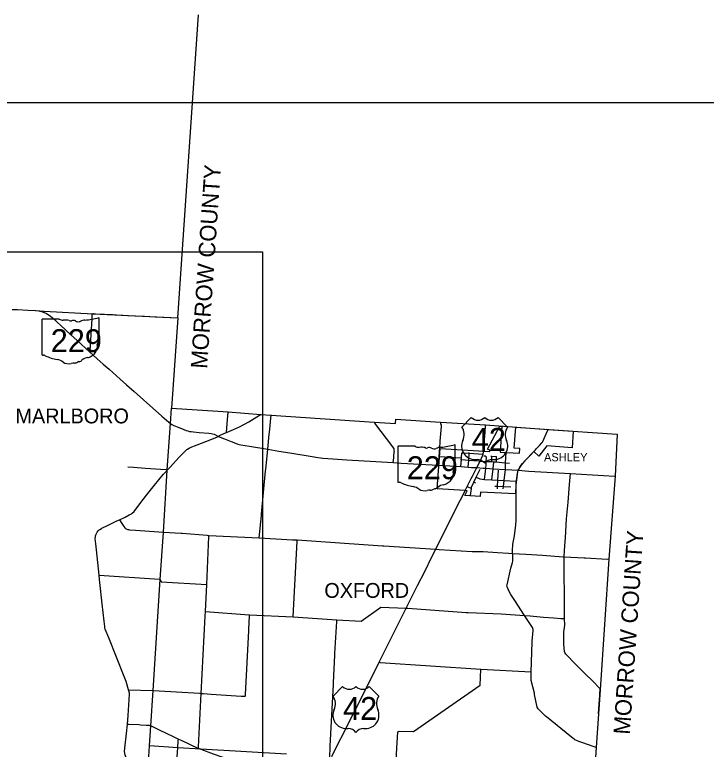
# Model space of a CAD drawing. Extents: x 1729596 to 1925846, y 659247 to 911751.
# Drawn here: x 1813555 to 1855559, y 860705 to 905333 of the extents above; entities that cross this region are included whole.
import ezdxf

# ---------------------------------------------------------------- set-up
doc = ezdxf.new("R2010")
doc.units = 0
for name, color, linetype in [('GM_X_Adjacent_County', 7, 'Continuous'), ('GM_X_Adjacent_County_Text', 7, 'Continuous'), ('GM_X_City_Street', 7, 'Continuous'), ('GM_X_Corporation', 7, 'Continuous'), ('GM_X_Corporation_Text', 7, 'Continuous'), ('GM_X_County', 7, 'Continuous'), ('GM_X_County_Road', 7, 'Continuous'), ('GM_X_State_Route', 7, 'Continuous'), ('GM_X_State_Shield', 7, 'Continuous'), ('GM_X_Township', 7, 'Continuous'), ('GM_X_Township_Road', 7, 'Continuous'), ('GM_X_Township_Text', 7, 'Continuous'), ('GM_X_US_Route', 7, 'Continuous'), ('GM_X_US_Shield', 7, 'Continuous'), ('SC_Scratch1', 7, 'Continuous'), ('SH_Data', 7, 'Continuous')]:
    doc.layers.add(name, color=color, linetype=linetype)

msp = doc.modelspace()

# ---------------------------------------------------------------- linework, layer by layer
at = {"layer": 'GM_X_Adjacent_County'}
msp.add_line((1823458, 886911), (1824723, 905333), dxfattribs=at)
at = {"layer": 'GM_X_City_Street'}
for points in [[(1845108, 878825), (1845186, 878908), (1845242, 878975), (1845432, 879171), (1845571, 879323), (1845601, 879368), (1845923, 880061), (1845958, 880137)], [(1840712, 878711), (1840771, 878720), (1841162, 878693), (1842005, 878635)], [(1841096, 877846), (1841141, 878272), (1841162, 878693), (1841165, 878729)], [(1843359, 877702), (1843365, 878107), (1843394, 878741)], [(1839341, 878485), (1840692, 878411)], [(1840624, 878310), (1840684, 878302), (1841141, 878272), (1841739, 878225)], [(1840655, 877877), (1840684, 878302), (1840692, 878411), (1840712, 878711)], [(1842195, 878194), (1842196, 878198), (1842207, 878423), (1842204, 878453), (1842189, 878476), (1842156, 878505), (1842118, 878523), (1842051, 878515)], [(1842480, 878523), (1842536, 878518), (1842809, 878492)], [(1842538, 878180), (1842536, 878518)], [(1842823, 878163), (1842809, 878492)], [(1841739, 878225), (1841815, 878219), (1842196, 878198), (1842538, 878180), (1842649, 878172), (1842823, 878163), (1843332, 878109)], [(1842164, 877756), (1842167, 877780), (1842180, 877986), (1842195, 878194)], [(1842531, 877075), (1842621, 877751), (1842649, 878172)], [(1843332, 878109), (1843335, 878108), (1843365, 878107), (1843598, 878093)], [(1841290, 876572), (1841275, 876591), (1841439, 876928), (1841591, 877241), (1841826, 877723)], [(1842082, 877102), (1842164, 877756)], [(1842882, 876677), (1842882, 876677), (1842882, 876684), (1842900, 877054), (1842928, 877653)], [(1843238, 876648), (1843241, 876673), (1843277, 877031), (1843359, 877702)], [(1841591, 877241), (1841805, 877127), (1842082, 877102), (1842094, 877101), (1842531, 877075), (1842900, 877054), (1843277, 877031), (1843995, 876989)], [(1841039, 876677), (1841303, 876558)], [(1841244, 876119), (1841303, 876558), (1841290, 876572)], [(1841439, 876928), (1841534, 876885)], [(1842709, 876689), (1842882, 876684), (1843220, 876674), (1843220, 876674)], [(1842875, 876522), (1842882, 876677)], [(1843220, 876674), (1843241, 876673), (1843680, 876660)], [(1843230, 876537), (1843238, 876642), (1843238, 876648)]]:
    msp.add_lwpolyline(points, dxfattribs=at)
at = {"layer": 'GM_X_Corporation'}
msp.add_lwpolyline([(1839212, 876522), (1839395, 878979), (1842403, 878797), (1842406, 878874), (1842276, 878944), (1843026, 880333), (1843137, 880326), (1843037, 878758), (1844222, 878701), (1844237, 878976), (1843894, 879006), (1843983, 880269), (1847478, 880034), (1847407, 879013), (1845866, 879149), (1845394, 878513), (1845080, 878796), (1844533, 878238), (1844393, 878064), (1844314, 877970), (1844271, 877898), (1844236, 877846), (1844178, 877730), (1844140, 877653), (1844101, 877578), (1844075, 877468), (1843989, 876865), (1843985, 876781), (1843972, 876227), (1841843, 876336), (1841816, 876073), (1840902, 876121), (1841027, 876414), (1840914, 876421)], close=True, dxfattribs=at)
at = {"layer": 'GM_X_County'}
msp.add_lwpolyline([(1813443, 887429), (1813717, 887422), (1814360, 887388), (1814847, 887358), (1815353, 887328), (1818316, 887169), (1823458, 886911), (1823082, 881429), (1826517, 881205), (1828513, 881052), (1829123, 881005), (1835395, 880574), (1836682, 880495), (1836708, 880754), (1839410, 880574), (1842150, 880416), (1845959, 880135), (1850147, 879854), (1850017, 877290), (1849634, 872258), (1849106, 864311), (1848864, 860810), (1848787, 859601)], dxfattribs=at)
at = {"layer": 'GM_X_County_Road'}
for points in [[(1826404, 879946), (1826423, 879954), (1826844, 880138), (1827215, 880304), (1827767, 880596), (1828264, 880901), (1828526, 881056)], [(1826423, 879954), (1826479, 880739), (1826518, 881195)], [(1822822, 877662), (1822979, 877822), (1823573, 878476), (1824013, 878909), (1824059, 878945), (1824151, 879002), (1824217, 879033), (1824631, 879211), (1825422, 879515), (1825871, 879688), (1825923, 879717)], [(1825923, 879717), (1825991, 879759), (1826404, 879946)], [(1844140, 877653), (1844178, 877730), (1844236, 877846), (1844271, 877898), (1844314, 877970), (1844393, 878064), (1844672, 878363), (1844876, 878580), (1845108, 878825)], [(1818695, 874040), (1818726, 874065), (1818820, 874127), (1818849, 874146), (1819230, 874331), (1819753, 874577), (1819917, 874653), (1820258, 874816), (1820515, 874948), (1820647, 875011), (1820694, 875046), (1820805, 875160), (1821161, 875608), (1821552, 876138), (1821797, 876450), (1822043, 876750), (1822580, 877393), (1822787, 877627), (1822822, 877662)], [(1844920, 865421), (1844988, 867215), (1844990, 867274), (1845035, 867925), (1845034, 867981), (1845022, 868042), (1845000, 868095), (1844527, 868834), (1843932, 869740), (1843693, 870106), (1843565, 870325), (1843478, 870530), (1843453, 870621), (1843455, 870702), (1843691, 871703), (1843783, 872054), (1843799, 872125), (1843808, 872218), (1843813, 872294), (1843800, 872513), (1843796, 872610), (1843794, 872719), (1843797, 872872), (1843799, 873058), (1843810, 873171), (1843903, 873683), (1843995, 874339), (1844011, 874603), (1844010, 875790), (1844011, 876128), (1844012, 876758), (1844119, 877561), (1844140, 877653)], [(1820462, 864324), (1820315, 864828), (1820199, 865126), (1819267, 867478), (1819059, 868009), (1819037, 868087), (1819024, 868161), (1818988, 868490), (1818871, 869545), (1818714, 871024), (1818688, 871275), (1818522, 872824), (1818481, 873185), (1818449, 873518), (1818456, 873613), (1818468, 873675), (1818498, 873766), (1818559, 873888), (1818627, 873984), (1818695, 874040)], [(1824699, 860768), (1824709, 860807), (1824715, 860860), (1824883, 864100), (1825114, 868796), (1825134, 869072), (1825228, 870716), (1825347, 873642), (1825350, 873697)], [(1825350, 873697), (1828404, 873550), (1830426, 873436), (1830706, 873421), (1835899, 873073), (1835968, 873069), (1839135, 872864)], [(1839135, 872864), (1839344, 872852), (1841345, 872730), (1841421, 872727), (1842003, 872716), (1842870, 872667), (1843552, 872620), (1843796, 872610)], [(1848869, 860822), (1848289, 861017), (1848127, 861070), (1847820, 861177), (1847644, 861252), (1847581, 861290), (1847540, 861317), (1847370, 861450), (1845855, 862679), (1845795, 862727), (1845378, 863132), (1845338, 863172), (1845282, 863256), (1845130, 864033), (1845116, 864109), (1844927, 864878), (1844914, 864930), (1844919, 865353), (1844920, 865421)], [(1819979, 856052), (1820004, 856221), (1820093, 856849), (1820106, 856948), (1820253, 859267), (1820256, 859321), (1820308, 860164), (1820312, 860243), (1820295, 860293), (1820272, 860358), (1820219, 860562), (1820238, 860767), (1820341, 861658), (1820408, 862232), (1820454, 862755), (1820524, 864057), (1820528, 864114), (1820480, 864265), (1820462, 864324)], [(1820408, 862232), (1820494, 862231), (1821085, 862203), (1821196, 862192), (1821533, 862179), (1821692, 862169), (1821732, 862161)], [(1821732, 862161), (1821747, 862158), (1821783, 862149), (1821820, 862138), (1821852, 862127), (1822363, 861870), (1822764, 861678), (1823175, 861477), (1823506, 861322), (1823697, 861236), (1824174, 861011), (1824367, 860911), (1824699, 860768)], [(1824699, 860768), (1824857, 860710), (1825612, 860430), (1826656, 860059), (1826853, 859982), (1826971, 859934), (1827258, 859768), (1827710, 859527), (1828254, 859247), (1828432, 859153), (1828513, 859123), (1828584, 859112), (1829052, 859088), (1829917, 859051), (1830145, 859048), (1831204, 858991), (1831412, 858982), (1831846, 858956), (1831978, 858953), (1832140, 858950)]]:
    msp.add_lwpolyline(points, dxfattribs=at)
at = {"layer": 'GM_X_State_Route'}
for points in [[(1813408, 887426), (1813443, 887429), (1813717, 887422), (1814360, 887388), (1814824, 887360)], [(1814824, 887360), (1814847, 887358), (1815015, 887333), (1815089, 887321), (1815189, 887294), (1815338, 887242), (1815486, 887171), (1815704, 887032), (1815841, 886918), (1816128, 886656), (1816355, 886449), (1816954, 885901), (1817356, 885538), (1818106, 884845), (1818568, 884430), (1818934, 884102), (1819283, 883790), (1819954, 883190), (1820355, 882842), (1820806, 882440), (1821377, 881933), (1822496, 880940), (1822775, 880699), (1822923, 880569), (1823026, 880489), (1823096, 880443), (1823229, 880369), (1823524, 880245), (1823681, 880185), (1823974, 880072), (1824071, 880043), (1824169, 880019), (1824269, 880002), (1824418, 879984), (1824766, 879955), (1825340, 879913), (1825491, 879897), (1825574, 879880), (1825668, 879848), (1825923, 879717), (1826289, 879572), (1826707, 879409), (1826973, 879302), (1827103, 879251), (1827193, 879225), (1827284, 879205), (1827814, 879113), (1828926, 878930), (1829588, 878819), (1830263, 878712), (1831616, 878486), (1831957, 878431), (1832136, 878410), (1832267, 878397), (1832870, 878356), (1833733, 878300), (1836550, 878131), (1837033, 878098), (1838904, 877988), (1839306, 877964)], [(1839306, 877964), (1840655, 877877), (1841096, 877846), (1841303, 877834)], [(1841303, 877834), (1841619, 877817)], [(1841619, 877817), (1842011, 877788), (1842144, 877781)], [(1842144, 877781), (1842167, 877780), (1842611, 877751), (1842621, 877751), (1843359, 877702), (1844140, 877653)], [(1844140, 877653), (1844783, 877609), (1847310, 877457), (1849978, 877293)]]:
    msp.add_lwpolyline(points, dxfattribs=at)
at = {"layer": 'GM_X_State_Shield'}
for p, q in [((1815205, 886800), (1815205, 884687)), ((1815205, 886800), (1815205, 884687)), ((1816258, 886837), (1815239, 886837)), ((1816258, 886837), (1815239, 886837)), ((1818685, 885784), (1818685, 886889)), ((1818685, 885784), (1818685, 886889)), ((1818685, 885784), (1818685, 885784)), ((1818685, 885784), (1818685, 885784)), ((1840307, 878062), (1840307, 879167)), ((1840307, 878062), (1840307, 879167)), ((1836826, 879078), (1836826, 876965)), ((1836826, 879078), (1836826, 876965)), ((1837880, 879115), (1836860, 879115)), ((1837880, 879115), (1836860, 879115)), ((1840306, 878062), (1840307, 878062)), ((1840306, 878062), (1840307, 878062))]:
    msp.add_line(p, q, dxfattribs=at)
for centre, major_axis, start_param, end_param in [((1815244, 886805), (40.3, 0), 1.712693, 3.28349), ((1815244, 886805), (40.3, 0), 1.712693, 3.28349), ((1816501, 887082), (391, 0), 4.042523, 4.731795), ((1816501, 887082), (391, 0), 4.042523, 4.731795), ((1816630, 885650), (1404, 0), 1.404758, 1.657858), ((1816630, 885650), (1404, 0), 1.404758, 1.657858), ((1816949, 886816), (113, 0), 3.836095, 5.185415), ((1816949, 886816), (113, 0), 3.836095, 5.185415), ((1817115, 886572), (235, 0), 0.950623, 2.079405), ((1817115, 886572), (235, 0), 0.950623, 2.079405), ((1817916, 886191), (743, 0), 1.699011, 2.107814), ((1817916, 886191), (743, 0), 1.699011, 2.107814), ((1817445, 889718), (3691, 0), 4.814394, 5.042369), ((1817445, 889718), (3691, 0), 4.814394, 5.042369), ((1818646, 886894), (38.7, 0), 6.141152, 7.989035), ((1818646, 886894), (38.7, 0), 6.141152, 7.989035), ((1817418, 886907), (282, 0), 4.081561, 5.145723), ((1817418, 886907), (282, 0), 4.081561, 5.145723), ((1818824, 885321), (262, 0), 2.387724, 3.262537), ((1818824, 885321), (262, 0), 2.387724, 3.262537), ((1818676, 885703), (60, 0), 1.883978, 3.671073), ((1818676, 885703), (60, 0), 1.883978, 3.671073), ((1818295, 885563), (360, 0), 5.934695, 6.695948), ((1818295, 885563), (360, 0), 5.934695, 6.695948), ((1818644, 885779), (41.5, 0), 5.05454, 6.418171), ((1818644, 885779), (41.5, 0), 5.05454, 6.418171), ((1817652, 885180), (923, 0), 5.101752, 6.440018), ((1817652, 885180), (923, 0), 5.101752, 6.440018), ((1815245, 884683), (40.7, 0), 3.00124, 4.508301), ((1815245, 884683), (40.7, 0), 3.00124, 4.508301), ((1815251, 884899), (310, 0), 4.665946, 4.897461), ((1815251, 884899), (310, 0), 4.665946, 4.897461), ((1815314, 884565), (112, 0), 0.519207, 1.627899), ((1815314, 884565), (112, 0), 0.519207, 1.627899), ((1816728, 886464), (2665, 0), 4.195997, 4.488961), ((1816728, 886464), (2665, 0), 4.195997, 4.488961), ((1815933, 883738), (834, 0), 0.823519, 1.323587), ((1815933, 883738), (834, 0), 0.823519, 1.323587), ((1816835, 884555), (529, 0), 4.026481, 4.996735), ((1816835, 884555), (529, 0), 4.026481, 4.996735), ((1817141, 883824), (435, 0), 1.495662, 1.94098), ((1817141, 883824), (435, 0), 1.495662, 1.94098), ((1817179, 884397), (282, 0), 4.691044, 5.507374), ((1817179, 884397), (282, 0), 4.691044, 5.507374), ((1817434, 884192), (79.4, 0), 1.147584, 2.315152), ((1817434, 884192), (79.4, 0), 1.147584, 2.315152), ((1817401, 884482), (298, 0), 4.937069, 5.64225), ((1817401, 884482), (298, 0), 4.937069, 5.64225), ((1818041, 884094), (506, 0), 1.647645, 2.488434), ((1818041, 884094), (506, 0), 1.647645, 2.488434), ((1839067, 881996), (3691, 0), 4.814394, 5.042369), ((1839067, 881996), (3691, 0), 4.814394, 5.042369), ((1840268, 879172), (38.7, 0), 6.141152, 7.989035), ((1840268, 879172), (38.7, 0), 6.141152, 7.989035), ((1836866, 879083), (40.3, 0), 1.712693, 3.28349), ((1836866, 879083), (40.3, 0), 1.712693, 3.28349), ((1838122, 879360), (391, 0), 4.042523, 4.731795), ((1838122, 879360), (391, 0), 4.042523, 4.731795), ((1838252, 877928), (1404, 0), 1.404758, 1.657858), ((1838252, 877928), (1404, 0), 1.404758, 1.657858), ((1838571, 879094), (113, 0), 3.836095, 5.185415), ((1838571, 879094), (113, 0), 3.836095, 5.185415), ((1838736, 878850), (235, 0), 0.950623, 2.079405), ((1838736, 878850), (235, 0), 0.950623, 2.079405), ((1839039, 879185), (282, 0), 4.081561, 5.145723), ((1839039, 879185), (282, 0), 4.081561, 5.145723), ((1839538, 878469), (743, 0), 1.699011, 2.107814), ((1839538, 878469), (743, 0), 1.699011, 2.107814), ((1840298, 877981), (60, 0), 1.883978, 3.671073), ((1840298, 877981), (60, 0), 1.883978, 3.671073), ((1839916, 877841), (360, 0), 5.934695, 6.695948), ((1839916, 877841), (360, 0), 5.934695, 6.695948), ((1840265, 878057), (41.5, 0), 5.05454, 6.418171), ((1840265, 878057), (41.5, 0), 5.05454, 6.418171), ((1839274, 877458), (923, 0), 5.101752, 6.440018), ((1839274, 877458), (923, 0), 5.101752, 6.440018), ((1840445, 877599), (262, 0), 2.387724, 3.262537), ((1840445, 877599), (262, 0), 2.387724, 3.262537), ((1836866, 876961), (40.7, 0), 3.00124, 4.508301), ((1836866, 876961), (40.7, 0), 3.00124, 4.508301), ((1836936, 876843), (112, 0), 0.519207, 1.627899), ((1836936, 876843), (112, 0), 0.519207, 1.627899), ((1836873, 877177), (310, 0), 4.665946, 4.897461), ((1836873, 877177), (310, 0), 4.665946, 4.897461), ((1838349, 878742), (2665, 0), 4.195997, 4.488961), ((1838349, 878742), (2665, 0), 4.195997, 4.488961), ((1837555, 876016), (834, 0), 0.823519, 1.323587), ((1837555, 876016), (834, 0), 0.823519, 1.323587), ((1838457, 876833), (529, 0), 4.026481, 4.996735), ((1838457, 876833), (529, 0), 4.026481, 4.996735), ((1838801, 876675), (282, 0), 4.691044, 5.507374), ((1838801, 876675), (282, 0), 4.691044, 5.507374), ((1839056, 876470), (79.4, 0), 1.147584, 2.315152), ((1839056, 876470), (79.4, 0), 1.147584, 2.315152), ((1839022, 876760), (298, 0), 4.937069, 5.64225), ((1839022, 876760), (298, 0), 4.937069, 5.64225), ((1839663, 876372), (506, 0), 1.647645, 2.488434), ((1839663, 876372), (506, 0), 1.647645, 2.488434), ((1838762, 876102), (435, 0), 1.495662, 1.94098), ((1838762, 876102), (435, 0), 1.495662, 1.94098)]:
    msp.add_ellipse(centre, major_axis=major_axis, ratio=0.8, start_param=start_param, end_param=end_param, dxfattribs=at)
at = {"layer": 'GM_X_Township'}
for points in [[(1830057, 860416), (1824857, 860710), (1823464, 860801), (1821743, 860915), (1821820, 862138), (1821956, 864281), (1822382, 871013), (1822583, 873901), (1822822, 877662), (1822932, 879384), (1823026, 880489), (1823082, 881429)], [(1850147, 879854), (1850017, 877290), (1849634, 872258), (1849106, 864311), (1848864, 860810), (1848787, 859601)], [(1820182, 834021), (1820274, 835623), (1820357, 837080), (1820411, 838018), (1820789, 844650), (1820950, 847472), (1821204, 851968), (1821306, 853784), (1821743, 860915)]]:
    msp.add_lwpolyline(points, dxfattribs=at)
at = {"layer": 'GM_X_Township_Road'}
for points in [[(1818106, 884845), (1818121, 884859), (1818133, 884883), (1818136, 884905), (1818252, 886879), (1818267, 887127), (1818268, 887136), (1818271, 887143), (1818274, 887150), (1818280, 887162)], [(1818280, 887162), (1818283, 887165), (1818289, 887169), (1818299, 887170), (1818316, 887171), (1818334, 887171), (1818481, 887161), (1819006, 887135), (1819514, 887112), (1819744, 887102), (1820121, 887082), (1820432, 887068), (1820842, 887046), (1821432, 887018), (1822088, 886984), (1822989, 886935), (1823461, 886911)], [(1828926, 878930), (1829014, 879840), (1829023, 879943), (1829130, 881016)], [(1836550, 878131), (1836572, 878407), (1836577, 878507), (1836605, 878769), (1836613, 878847), (1836605, 878899), (1836595, 878967), (1836565, 879011), (1836515, 879086), (1835436, 880521), (1835397, 880584)], [(1839306, 877964), (1839341, 878485), (1839399, 879352), (1839403, 879417), (1839467, 880312), (1839471, 880374), (1839440, 880475), (1839429, 880574)], [(1828404, 873550), (1828535, 874900), (1828545, 874985), (1828797, 877614), (1828805, 877701), (1828926, 878930)], [(1820435, 877874), (1820766, 877848), (1821496, 877793), (1822410, 877722), (1822732, 877701), (1822772, 877694), (1822797, 877688), (1822822, 877662)], [(1846952, 868642), (1846950, 869189), (1846940, 869904), (1846940, 870264), (1846936, 871157), (1846927, 871876), (1846924, 872189), (1846924, 872391), (1846924, 872409), (1846974, 873096), (1847017, 873560), (1847077, 874700), (1847167, 875719), (1847252, 876799), (1847310, 877457)], [(1819917, 874653), (1820070, 874430), (1820190, 874250), (1820246, 874169), (1820290, 874124), (1820359, 874086), (1820425, 874058), (1820460, 874051)], [(1820460, 874051), (1820518, 874039), (1820891, 874015), (1822583, 873901), (1822593, 873900)], [(1822593, 873900), (1823661, 873833), (1823727, 873829), (1825253, 873705), (1825350, 873697)], [(1830464, 868756), (1830701, 873344), (1830706, 873421)], [(1843796, 872610), (1844591, 872563), (1845606, 872508), (1846865, 872395), (1846924, 872391), (1848139, 872336), (1848226, 872331), (1849545, 872262), (1849640, 872268)], [(1818688, 871275), (1822342, 871039), (1822367, 871038)], [(1822367, 871038), (1822368, 871038), (1822382, 871013), (1822458, 870878), (1825228, 870716)], [(1825134, 869072), (1827790, 868881), (1827808, 868880), (1830464, 868756), (1833115, 868570), (1834606, 868488), (1835796, 869350), (1837331, 869279), (1837434, 869271)], [(1837434, 869271), (1840984, 869021), (1841014, 869019), (1841088, 869014), (1843104, 868927), (1844527, 868834), (1844860, 868817), (1845680, 868730), (1846299, 868685), (1846723, 868656), (1846952, 868642)], [(1824883, 864100), (1825008, 864087), (1825479, 864057), (1827301, 863943), (1827512, 863928), (1827528, 863927), (1827544, 863932), (1827556, 863942), (1827563, 863956), (1827574, 864035), (1827772, 867912), (1827777, 867978), (1827806, 868822), (1827808, 868880)], [(1832712, 860086), (1832692, 860180), (1832694, 860243), (1832711, 860815), (1832717, 860894), (1832916, 864638), (1832920, 864735), (1833003, 866422), (1833008, 866525), (1833111, 868476), (1833115, 868570)], [(1847190, 866322), (1847029, 866494), (1846966, 866586), (1846940, 866643), (1846902, 867096), (1846899, 867328), (1846913, 867520), (1846901, 867711), (1846907, 867849), (1846949, 868098), (1846958, 868238), (1846952, 868642)], [(1849108, 864379), (1849086, 864409), (1849077, 864422), (1849056, 864444), (1848707, 864795), (1848132, 865354), (1847476, 866016), (1847190, 866322)], [(1835681, 865996), (1835751, 865973), (1841870, 865582), (1844920, 865421)], [(1836801, 859906), (1836785, 859928), (1836730, 860003), (1836772, 860771), (1836832, 861759), (1836900, 861806), (1837774, 861777), (1841815, 864609), (1841870, 865582)], [(1820462, 864324), (1821937, 864282)], [(1821937, 864282), (1821956, 864281), (1821991, 864279), (1823727, 864175), (1824431, 864135), (1824774, 864114), (1824883, 864100)], [(1849021, 862856), (1849057, 863463), (1849090, 863978), (1849102, 864092), (1849117, 864321), (1849117, 864329), (1849117, 864338), (1849117, 864343), (1849117, 864351), (1849116, 864355), (1849116, 864358), (1849115, 864361), (1849113, 864368), (1849111, 864373), (1849108, 864379)], [(1823464, 860797), (1823464, 860801), (1823489, 861218), (1823506, 861322)], [(1822973, 852697), (1823090, 854855), (1823095, 854950), (1823360, 859378), (1823364, 859462), (1823464, 860797)]]:
    msp.add_lwpolyline(points, dxfattribs=at)
at = {"layer": 'GM_X_US_Route'}
for points in [[(1842050, 878929), (1842054, 878989), (1842074, 879275), (1842125, 879970), (1842151, 880391)], [(1842000, 878620), (1842005, 878635), (1842013, 878659), (1842035, 878764), (1842042, 878816), (1842050, 878929)], [(1841619, 877817), (1841815, 878219), (1841969, 878528), (1842000, 878620)], [(1841285, 877158), (1841355, 877293), (1841619, 877817)], [(1840905, 876404), (1840914, 876421), (1841039, 876677), (1841285, 877158)], [(1832814, 860270), (1833045, 860728), (1833707, 862039), (1833995, 862623), (1834269, 863162), (1835215, 865051), (1835681, 865996), (1836078, 866774), (1836442, 867502), (1837331, 869279), (1837642, 869882), (1838022, 870648), (1838475, 871555), (1838873, 872351), (1839135, 872864), (1840316, 875226), (1840905, 876404)]]:
    msp.add_lwpolyline(points, dxfattribs=at)
at = {"layer": 'GM_X_US_Shield'}
for p, q in [((1841287, 880866), (1840707, 880285)), ((1841287, 880866), (1840707, 880285)), ((1843491, 880285), (1842911, 880866)), ((1843491, 880285), (1842911, 880866)), ((1841519, 878313), (1841635, 878313)), ((1841519, 878313), (1841635, 878313)), ((1842563, 878313), (1842679, 878313)), ((1842563, 878313), (1842679, 878313)), ((1833468, 864520), (1832888, 863940)), ((1833468, 864520), (1832888, 863940)), ((1835673, 863940), (1835092, 864520)), ((1835673, 863940), (1835092, 864520)), ((1833700, 861967), (1833816, 861967)), ((1833700, 861967), (1833816, 861967)), ((1834744, 861967), (1834860, 861967)), ((1834744, 861967), (1834860, 861967))]:
    msp.add_line(p, q, dxfattribs=at)
for centre, radius, start, end in [((1841693, 881280), 580, 225.573, 314.427), ((1841693, 881280), 580, 225.573, 314.427), ((1842505, 881280), 580, 225.573, 314.427), ((1842505, 881280), 580, 225.573, 314.427), ((1840042, 879820), 812, 334.5471, 35.0009), ((1840042, 879820), 812, 334.5471, 35.0009), ((1844157, 879820), 812, 144.9991, 205.4529), ((1844157, 879820), 812, 144.9991, 205.4529), ((1841510, 879125), 812, 154.8319, 270.6383), ((1841510, 879125), 812, 154.8319, 270.6383), ((1842688, 879125), 812, 269.3617, 25.1681), ((1842688, 879125), 812, 269.3617, 25.1681), ((1841635, 877733), 580, 36.8699, 90), ((1841635, 877733), 580, 36.8699, 90), ((1842563, 877733), 580, 90, 143.1301), ((1842563, 877733), 580, 90, 143.1301), ((1833874, 864934), 580, 225.573, 314.427), ((1833874, 864934), 580, 225.573, 314.427), ((1834686, 864934), 580, 225.573, 314.427), ((1834686, 864934), 580, 225.573, 314.427), ((1832223, 863474), 812, 334.5471, 35.0009), ((1832223, 863474), 812, 334.5471, 35.0009), ((1836338, 863474), 812, 144.9991, 205.4529), ((1836338, 863474), 812, 144.9991, 205.4529), ((1833691, 862779), 812, 154.8319, 270.6383), ((1833691, 862779), 812, 154.8319, 270.6383), ((1834869, 862779), 812, 269.3617, 25.1681), ((1834869, 862779), 812, 269.3617, 25.1681), ((1833816, 861387), 580, 36.8699, 90), ((1833816, 861387), 580, 36.8699, 90), ((1834744, 861387), 580, 90, 143.1301), ((1834744, 861387), 580, 90, 143.1301)]:
    msp.add_arc(centre, radius, start, end, dxfattribs=at)
at = {"layer": 'SC_Scratch1'}
msp.add_lwpolyline([(1729596, 899996), (1925846, 899996), (1925846, 765496), (1729596, 765496)], close=True, dxfattribs=at)
at = {"layer": 'SH_Data'}
for p, q in [((1752099, 890928), (1828599, 890928)), ((1828599, 890928), (1828599, 814428))]:
    msp.add_line(p, q, dxfattribs=at)

# ---------------------------------------------------------------- texts
at = {"layer": 'GM_X_Adjacent_County_Text'}
for rotation, p in [(86.0902, (1825240, 883804)), (86.16, (1850915, 861578))]:
    msp.add_text('MORROW COUNTY', height=1000, rotation=rotation, dxfattribs=at).set_placement(p)
at = {"layer": 'GM_X_Corporation_Text'}
msp.add_text('ASHLEY', height=500, rotation=0, dxfattribs=at).set_placement((1845704, 878201))
at = {"layer": 'GM_X_State_Shield'}
for p in [(1815744, 884836), (1815744, 884836), (1837366, 877114), (1837366, 877114)]:
    msp.add_text('229', height=1392.2, dxfattribs=at).set_placement(p)
at = {"layer": 'GM_X_Township_Text'}
for s, p in [('MARLBORO', (1813603, 880507)), ('OXFORD', (1832362, 869907))]:
    msp.add_text(s, height=900, rotation=0, dxfattribs=at).set_placement(p)
at = {"layer": 'GM_X_US_Shield'}
for p in [(1841315, 878835), (1841315, 878835), (1833497, 862489), (1833497, 862489)]:
    msp.add_text('42', height=1392.2, dxfattribs=at).set_placement(p)

doc.saveas('drawing.dxf')
